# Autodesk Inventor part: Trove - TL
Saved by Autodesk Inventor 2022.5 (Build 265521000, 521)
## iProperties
Created: 2024-07
Part Number: Trove - TL
Material: Generic
Document SubType Name: Modeling
Designer: AdminForWorker
Density: 1 g/cm^3
Appearance: Default
Title: Trove - TL
Author: AdminForWorker
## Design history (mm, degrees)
feature "Trove - TL"
body "Solid1"
